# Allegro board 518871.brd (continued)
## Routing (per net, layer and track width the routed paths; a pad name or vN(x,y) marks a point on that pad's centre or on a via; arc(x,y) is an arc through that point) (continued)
VOUT3B_D1: length 45.9
  TOP w0.102: U27.E2 56.68,76.87 56.95,77.14 58.09,77.14
  TOP w0.127: v1(79.76,76.03) 68.92,76.03 68.8,75.91 64.43,75.91 63.92,76.42 60.49,76.42 59.76,77.14 58.09,77.14 ; SW1.11 v1(79.76,78.74)
  LY3 w0.133: v1(79.76,78.74) 80.24,79.22 81.31,79.22 83.1,77.43 85.3,77.43 85.72,77.85 89.66,77.85 89.92,77.6 91.31,77.6 92.84,79.12 93.7,79.12 v1(93.82,79.25)
  BOTTOM w0.127: 93.82,80.64 v1(93.82,79.25) ; v1(79.76,76.03) v1(79.76,78.74) R255.1
VOUT3B_D2: length 44.1
  TOP w0.127: SW1.10 v1(78.49,78.74) ; v1(78.49,75.44) 78.27,75.65 63.92,75.65 63.41,76.16 60.24,76.16 59.56,76.84 U27.E1
  LY3 w0.133: v1(78.49,78.74) 79.23,79.48 81.55,79.48 82.55,78.49 85.85,78.49 86.14,78.2 89.82,78.2 90.05,77.97 91.31,77.97 92.82,79.49 v1(92.82,79.9)
  BOTTOM w0.127: v1(78.49,75.44) v1(78.49,78.74) R251.1 ; 92.82,80.64 v1(92.82,79.9)
VOUT3B_D3: length 44.3
  TOP w0.127: v1(77.22,74.93) 76.52,74.23 63.31,74.23 62.86,74.68 59.56,74.68 58.7,75.54 U27.C1 ; SW1.9 v1(77.22,78.74)
  LY3 w0.133: v1(77.22,78.74) 78.22,79.74 81.8,79.74 82.68,78.87 86.11,78.87 86.52,78.46 90.07,78.46 90.3,78.23 90.93,78.23 v1(91.82,79.12)
  BOTTOM w0.127: v1(91.82,79.12) 92.32,79.62 92.32,80.64 ; v1(77.22,74.93) v1(77.22,78.74) R247.1
VOUT3B_D4: length 43.6
  TOP w0.127: U27.D1 59.19,76.19 59.94,75.44 63.12,75.44 63.63,74.93 72.26,74.93 72.47,75.14 75.74,75.14 v1(75.95,74.93) ; SW1.8 v1(75.95,78.74)
  LY3 w0.133: v1(75.95,78.74) 77.21,80 82.05,80 82.8,79.25 86.36,79.25 86.87,78.74 90.3,78.74 90.42,78.61 90.93,78.61 91.31,78.99 91.31,79.38 v1(91.83,79.89)
  BOTTOM w0.127: R243.1 v1(75.95,78.74) v1(75.95,74.93) ; 91.83,80.64 v1(91.83,79.89)
VOUT3B_D5: length 43.7
  TOP w0.102: 58.09,75.86 57.01,75.86 U27.D2
  TOP w0.127: 58.09,75.86 58.88,75.86 59.69,75.06 62.99,75.06 63.37,74.68 74.63,74.68 v1(74.68,74.72) ; SW1.7 v1(74.68,78.74)
  LY3 w0.133: v1(74.68,78.74) 76.2,80.26 82.3,80.26 82.93,79.63 86.61,79.63 87.12,79.12 v1(90.81,79.12)
  BOTTOM w0.127: v1(74.68,74.72) v1(74.68,78.74) R241.1 ; v1(90.81,79.12) 91.33,79.64 91.33,80.64
VOUT3B_D6: length 43.9
  TOP w0.127: U27.B1 58.33,74.89 59.31,73.91 62.61,73.91 63.12,73.41 77.6,73.41 78.11,73.91 81.41,73.91 81.79,73.53 v1(81.79,73.49)
  LY4 w0.133: v1(81.79,73.49) 81.79,73.91 81.63,74.06 81.18,74.06 81.03,74.22 81.03,74.44 81.18,74.6 81.63,74.6 81.79,74.75 81.79,74.97 81.45,75.31 81.45,76.67 81.18,76.93 81.18,78.13 81.53,78.49 81.53,78.99 81.18,79.35 81.18,80.67 81.53,81.03 81.53,82.3 82.42,83.19 v1(83.44,83.19)
  BOTTOM w0.127: U77.23 86.5,84.34 85.34,83.19 v1(83.44,83.19) 83.44,83.44 RJ25.2
VOUT3B_D7: length 43.5
  TOP w0.127: v1(81.03,73.41) 80.64,73.03 63.08,73.03 62.57,73.53 59.18,73.53 58.16,74.56 57.27,74.56 57.25,74.58 57.2,74.58 56.88,74.89 U27.B2
  LY4 w0.133: v1(83.44,84.45) 82.55,84.45 80.39,82.3 80.39,74.04 v1(81.03,73.41)
  BOTTOM w0.127: U77.24 86.11,84.84 85.72,84.45 v1(83.44,84.45) 83.44,84.71 RJ24.2
VOUT3B_D8: length 56.6
  TOP w0.102: 58.09,75.21 57.01,75.21 U27.C2
  TOP w0.127: 58.09,75.21 58.52,75.21 59.44,74.3 62.74,74.3 63.12,73.91 77.34,73.91 77.98,74.55 91.06,74.55 93.34,76.83 99.19,76.83 v1(100.08,77.72)
  BOTTOM w0.127: U77.60 98.4,83.34 98.83,82.91 99.92,82.91 100.46,83.44 101.35,82.55 101.35,81.03 100.08,79.76 v1(100.08,77.72)
VOUT3B_D9: length 53.2
  TOP w0.102: 58.09,76.49 56.34,76.49 U27.D3
  TOP w0.127: v1(99.06,77.6) 98.55,77.09 91.57,77.09 89.41,74.93 78.11,74.93 77.64,75.4 72.37,75.4 72.28,75.31 63.75,75.31 63.25,75.82 60.07,75.82 59.4,76.49 58.09,76.49
  BOTTOM w0.127: v1(99.06,77.6) 99.31,77.85 99.31,81.66 RJ16.2 99.16,82.58 98.4,82.58 98.13,82.84 U77.61
VOUT3B_D10: length 53
  TOP w0.127: U27.A2 56.68,73.45 57.86,72.27 58.22,72.27 58.34,72.39 v1(63.12,72.39)
  LY3 w0.133: v1(63.12,72.39) 64.26,73.53 79.88,73.53 80.52,74.17 93.98,74.17 94.61,74.8 94.61,75.31 95.5,76.2 v1(98.3,76.2)
  BOTTOM w0.127: v1(98.3,76.2) 98.3,76.45 RJ20.2 98.68,77.34 97.58,78.44 97.58,80.82 97.92,81.15 97.92,82.17 97.75,82.33 96.53,82.33 U77.62
VOUT3B_D11: length 49.9
  TOP w0.102: 56.35,73.51 56.35,74.38 56.03,74.7 U27.B3
  TOP w0.127: v1(62.48,71.97) 62.45,72.01 57.76,72.01 56.35,73.41 56.35,73.51
  LY3 w0.133: v1(62.48,71.97) 62.52,71.97 62.57,71.92 63.8,71.92 65.14,73.27 80.13,73.27 80.77,73.91 83.95,73.91 84.33,73.53 94.74,73.53 v1(96.14,74.93)
  BOTTOM w0.127: v1(96.14,74.93) 96.14,75.18 RJ21.2 96.77,75.82 96.77,77.72 95.82,78.67 95.82,80.64
VOUT3B_D12: length 46.3
  TOP w0.102: U27.C3 56.36,75.21 56.36,74.74 56.53,74.57 56.81,74.57 57.01,74.38 57.01,73.88 57.38,73.51
  TOP w0.127: 57.38,73.51 57.63,73.25 58.09,73.25 58.45,72.9 v1(62.61,72.9)
  LY3 w0.133: v1(62.61,72.9) 63.63,73.91 79.76,73.91 80.35,74.51 92.8,74.51 v1(94.55,76.26)
  BOTTOM w0.127: 95.32,80.64 95.32,78.81 95.12,78.61 RJ19.2 v1(94.55,76.26)
VOUT3B_D13: length 44.5
  TOP w0.127: U27.C4 v3(55.7,75.22)
  LY3 w0.133: v1(92.33,74.93) 80.26,74.93 79.63,74.3 56.63,74.3 v3(55.7,75.22)
  BOTTOM w0.127: v1(92.33,74.93) RJ22.2 92.96,77.22 94.87,79.12 94.87,80.14 94.82,80.18 94.82,80.64
VOUT3B_D14: length 43.9
  TOP w0.127: v1(61.98,71.12) 60.33,71.12 59.69,71.75 57.65,71.75 56.03,73.38 U27.A3
  LY3 w0.133: v1(83.44,73.41) 82.55,73.41 82.04,72.9 65.66,72.9 64.3,71.54 62.4,71.54 v1(61.98,71.12)
  LY4 w0.133: v1(83.44,73.41) v1(83.44,80.64)
  BOTTOM w0.127: U77.21 86.9,83.34 85.85,82.3 85.85,81.53 84.96,80.64 v1(83.44,80.64) 83.44,80.9 RJ18.2
VOUT3B_D15: length 46.5
  TOP w0.102: 56.17,72.87 55.68,73.37 55.68,74.59 U27.B4
  TOP w0.127: v1(61.72,70.23) 59.94,70.23 58.67,71.5 57.55,71.5 56.17,72.87
  LY3 w0.133: v1(61.72,70.23) 63.75,70.23 66.04,72.52 82.42,72.52 v1(82.8,72.9)
  LY4 w0.133: v1(82.8,72.9) 82.8,81.28 v1(83.44,81.92)
  BOTTOM w0.127: U77.22 86.51,83.84 85.47,82.8 85.47,82.3 85.09,81.92 v1(83.44,81.92) 83.44,82.17 RJ23.2
VOUT3B_D16: length 50.9
  TOP w0.102: U27.M1 58.94,81.39 59.18,81.15 59.36,81.15
  TOP w0.127: v1(98.55,87.38) 98.55,85.98 98.15,85.57 96.88,85.57 95.12,83.82 95.12,82.8 93.47,81.15 90.17,81.15 88.77,79.76 83.57,79.76 83.02,80.3 83.02,81.19 81.66,82.55 72.77,82.55 71.25,81.03 68.92,81.03 68.63,80.73 65.9,80.73 65.87,80.7 65.52,80.7 65.5,80.73 62.4,80.73 62.28,80.61 61.93,80.61 61.38,81.15 59.36,81.15
  BOTTOM w0.127: U77.53 97.4,86.84 97.43,86.87 98.04,86.87 v1(98.55,87.38)
VOUT3B_D17: length 47.6
  TOP w0.102: 59.44,81.41 59.15,81.69 56.98,81.69 U27.M2
  TOP w0.127: v1(97.79,86.11) 97.51,85.83 96.64,85.83 94.87,84.05 94.87,83.06 93.35,81.53 90.04,81.53 88.65,80.14 84.84,80.14 83.69,81.28 83.31,81.28 81.66,82.93 72.64,82.93 71.29,81.57 61.76,81.57 61.59,81.41 59.44,81.41
  BOTTOM w0.127: v1(97.79,86.11) 97.52,85.84 U77.55
VOUT3B_D18: length 49.6
  TOP w0.102: U27.L2 56.98,81.04 58.66,81.04 58.8,80.9
  TOP w0.127: 58.8,80.9 58.89,80.81 61.18,80.81 61.63,80.35 62.57,80.35 62.67,80.45 65.98,80.45 66.01,80.48 71.21,80.48 72.9,82.17 81.66,82.17 82.68,81.15 82.68,80.01 83.31,79.38 88.9,79.38 90.3,80.77 93.73,80.77 95.38,82.42 95.38,83.57 97.07,85.26 97.75,85.26 v1(98.17,84.84)
  BOTTOM w0.127: v1(98.17,84.84) 97.67,85.34 U77.56
VOUT3B_D19: length 47.1
  TOP w0.102: U27.L1 58.45,80.74 58.61,80.58
  TOP w0.127: v1(97.4,84.84) 97.01,84.84 95.63,83.46 95.63,82.17 93.85,80.39 90.55,80.39 89.15,78.99 83.19,78.99 82.17,80.01 82.17,80.73 81.11,81.79 73.02,81.79 71.37,80.14 68.96,80.14 68.36,79.54 62.95,79.54 62.61,79.88 60.83,79.88 60.2,80.52 58.67,80.52 58.61,80.58
  BOTTOM w0.127: U77.57 v1(97.4,84.84)
VOUT3B_D20: length 47.1
  TOP w0.127: U27.K3 v3(56.36,79.77)
  LY3 w0.102: 58.09,79.77 v3(56.36,79.77)
  LY3 w0.133: 58.09,79.77 59.8,79.77 60.96,78.61 73.03,78.61 74.94,80.52 82.54,80.52 82.93,80.14 84.45,80.14 86.11,81.79 96.14,81.79 v1(98.17,83.82)
  BOTTOM w0.127: v1(98.17,83.82) 97.65,84.34 U77.58
VOUT3B_D21: length 46.8
  TOP w0.102: 58.55,80.14 58.29,80.39 56.98,80.39 U27.K2
  TOP w0.127: v1(97.39,83.84) 96.92,83.84 95.89,82.8 95.89,81.79 94.36,80.26 94.09,80.26 92.43,78.61 81.66,78.61 81.28,78.23 74.42,78.23 74.04,78.61 74.04,79.25 73.53,79.76 69.09,79.76 68.45,79.12 66.23,79.12 65.82,78.71 63.02,78.71 62.1,79.63 60.58,79.63 60.07,80.14 58.55,80.14
  BOTTOM w0.127: U77.59 v1(97.39,83.84)
VOUT3B_D22: length 45.3
  TOP w0.127: U27.J1 57.72,79.44 58.17,78.99 59.69,78.99 60.07,78.61 61.72,78.61 62.39,77.95 66.12,77.95 66.27,77.8 66.27,77.49 66.42,77.34 66.63,77.34 66.78,77.49 66.78,77.8 66.93,77.95 67.14,77.95 67.29,77.8 67.29,77.49 67.44,77.34 67.65,77.34 67.8,77.49 67.8,77.8 67.95,77.95 69.58,77.95 69.73,77.8 69.73,77.36 69.88,77.22 70.09,77.22 70.24,77.36 70.24,77.8 70.39,77.95 70.6,77.95 70.75,77.8 70.75,77.36 70.89,77.22 71.1,77.22 71.25,77.36 71.25,77.8 71.4,77.95 71.61,77.95 71.76,77.8 71.76,77.36 71.91,77.22 72.12,77.22 72.27,77.36 72.27,77.8 72.42,77.95 72.67,77.95 73.41,77.22 v1(86.11,77.22)
  BOTTOM w0.127: v1(86.11,77.22) 86.61,77.72 86.61,77.98 86.47,78.13 85.49,78.13 85.34,78.28 85.34,78.49 85.49,78.63 86.47,78.63 86.61,78.78 86.61,78.99 86.47,79.14 85.49,79.14 85.34,79.29 85.34,79.5 85.49,79.65 86.47,79.65 86.61,79.8 86.61,81.92 87.04,82.34 U77.19
VOUT3B_D23: length 44.9
  TOP w0.102: 58.42,79.76 58.08,80.09 U27.K1
  TOP w0.127: 58.42,79.76 59.94,79.76 60.45,79.25 61.98,79.25 62.77,78.46 65.93,78.46 66.08,78.61 69.43,78.61 69.57,78.76 69.57,79.23 69.72,79.38 69.93,79.38 70.08,79.23 70.08,78.76 70.23,78.61 70.44,78.61 70.59,78.76 70.59,79.23 70.74,79.38 70.95,79.38 71.1,79.23 71.1,78.76 71.25,78.61 71.46,78.61 71.61,78.76 71.61,79.23 71.75,79.38 71.97,79.38 72.11,79.23 72.11,78.76 72.26,78.61 72.47,78.61 72.62,78.76 72.62,79.23 72.77,79.38 72.98,79.38 73.13,79.23 73.13,78.76 73.91,77.98 v1(83.95,77.98)
  BOTTOM w0.127: v1(83.95,77.98) 84.71,77.98 84.84,78.11 84.84,78.4 84.69,78.55 82.06,78.55 81.92,78.69 81.92,78.91 82.06,79.05 84.69,79.05 84.84,79.2 84.84,80.01 86.23,81.41 86.23,81.92 87.16,82.84 U77.20
VOUT3B_DE: length 44.4
  TOP w0.102: 58.17,79.5 57.91,79.76 56.99,79.76 U27.J2
  TOP w0.127: 58.17,79.5 58.29,79.38 59.82,79.38 60.32,78.87 61.85,78.87 62.51,78.2 73.05,78.2 73.7,77.56 85.56,77.56 85.72,77.72 86.61,77.72 v1(87.12,77.22)
  BOTTOM w0.127: U77.18 87.17,81.84 87,81.66 87,80.14 87.12,80.01 87.12,79.62 87.27,79.47 89.01,79.47 89.15,79.32 89.15,79.11 89.01,78.96 87.27,78.96 87.12,78.82 87.12,78.61 87.27,78.46 89.01,78.46 89.15,78.31 89.15,78.1 89.01,77.95 87.27,77.95 87.12,77.8 v1(87.12,77.22)
VOUT3B_HSYNC: length 40.7
  TOP w0.127: U27.K4 v3(55.71,79.77)
  LY3 w0.102: v3(55.71,79.77) 56.1,79.38 58.09,79.38
  LY3 w0.133: 58.09,79.38 59.56,79.38 60.71,78.23 62.74,78.23 63.25,77.72 65.35,77.72 65.49,77.87 81.26,77.87 83.06,76.07 89.28,76.07 v1(89.98,76.77)
  BOTTOM w0.127: v1(89.98,76.77) 90.33,77.12 90.33,80.64
VOUT3B_VSYNC: length 44.5
  TOP w0.127: v1(89.03,77.22) 88.61,76.8 88.22,76.8 88.07,76.65 88.07,75.97 87.92,75.82 87.71,75.82 87.56,75.97 87.56,76.65 87.41,76.8 87.2,76.8 87.05,76.65 87.05,75.97 86.9,75.82 86.69,75.82 86.55,75.97 86.55,76.65 86.4,76.8 86.19,76.8 86.04,76.65 86.04,75.97 85.89,75.82 85.68,75.82 85.53,75.97 85.53,76.65 85.38,76.8 85.17,76.8 85.02,76.65 85.02,75.97 84.87,75.82 84.66,75.82 84.51,75.97 84.51,76.65 84.36,76.8 84.15,76.8 84.01,76.65 84.01,75.97 83.86,75.82 83.65,75.82 83.5,75.97 83.5,76.65 83.35,76.8 68.75,76.8 68.47,77.08 65.29,77.08 64.77,77.6 62.36,77.6 61.59,78.36 59.82,78.36 59.56,78.61 57.91,78.61 57.73,78.79 U27.H1
  BOTTOM w0.127: v1(89.03,77.22) 89.83,78.01 89.83,80.64
VREF_DBG: length 21.4
  TOP w0.203: 83.57,51.44 83.57,49.02 83.19,48.64 83.19,46.61 82.72,46.14 82.72,45.09 80.56,42.93 78.49,42.93 77.98,43.43 76.76,43.43 76.25,43.94 J14.12
  TOP w0.305: J14.1 79.32,51.51 79.63,51.82 81.28,51.82 81.66,51.44 83.57,51.44
VSYS_3V3: length 6.2
  TOP w0.305: U600.4 v1(64.77,97.03) ; U42.4 v1(73.1,25.32) ; 40.51,17.91 v1(40.51,17.08) ; R22.2 v1(34.04,17.21) ; C554.2 v1(36.32,29.59) ; U603.3 v1(63.83,103.94)
  BOTTOM w0.305: v1(36.32,29.59) 36.34,29.61 U76.4 ; R217.2 37.21,20.07 36.96,19.81 36.96,19.8 v1(36.95,19.79)
  vias: v1(13.46,45.47) v1(13.59,44.58) v1(13.72,27.05) v1(14.73,33.66) v1(14.99,44.2) v1(15.24,27.05) v1(15.75,33.66) v1(15.88,44.2) v1(16.76,33.66) v1(17.78,33.66) v1(18.8,33.66) v1(35.18,57.66) v1(35.18,47.12) v1(35.94,57.66) v1(36.2,56.9) v1(36.2,55.75) v1(36.2,49.02) v1(36.21,48.01) v1(36.2,47.12) v1(36.83,57.66) v1(36.96,56.39) v1(36.96,48.39) v1(36.96,47.37) v1(38.35,58.55) v1(39.12,58.55) v1(42.42,56.39) v1(42.42,48.39) v1(42.42,47.12) v1(42.49,57.53) v1(42.93,49.02) v1(42.93,47.75) v1(43.05,56.9) v1(43.05,55.88) v1(63.75,92.96) v1(64.26,94.49) v1(64.26,93.6) v1(67.56,104.01) v1(68.58,35.94) v1(68.71,28.32) v1(69.47,35.94) v1(69.6,28.32) v1(70.1,34.42) v1(70.61,35.94) v1(74.3,104.01)
VSYS_5V0: length 21.8
  TOP w0.203: v1(46.1,111.12) 46.41,111.43 U17.10
  TOP w0.305: C617.2 v1(72.26,92.96) U604.2 ; 73.1,20.95 TP51.1 ; TP51.1 74.47,20.95 ; TP51.1 73.79,20.27 ; TP51.1 73.79,21.64 ; U18.16 33.65,18.93 v1(34.04,18.54) ; R31.1 R30.2 ; R30.2 R28.2 ; R30.2 v1(42.55,112.14) ; U601.4 v1(70.79,32.64) ; U70.4 v1(110.57,85.9) ; R143.2 v1(74.3,30.73) ; U79.3 v1(102.87,59.56)
  LY3 w0.635: TP51.1 73.79,21.64 ; TP51.1 74.47,20.95 ; TP51.1 73.1,20.95 ; TP51.1 73.79,20.27
  BOTTOM w0.203: v1(46.1,111.12) C269.1
  BOTTOM w0.305: v1(74.17,93.73) 74.17,94.11 R606.2 ; v1(46.1,111.12) 45.59,111.12 45.21,110.74 43.94,110.74 v1(42.55,112.14) ; C514.1 v1(102.87,59.56)
  vias: v1(72.9,23.5) v1(72.9,22.73) v1(72.9,21.46) v1(72.9,20.45) v1(75.06,21.46)
VTT_DDR:
  vias: v1(5.08,67.31) v1(7.24,67.31) v1(10.03,67.31) v1(10.67,56.26) v1(10.67,55.24) v1(10.67,54.1) v1(10.67,53.09) v1(10.67,51.94) v1(10.67,50.93) v1(11.68,49.78) v1(12.7,67.31) v1(15.37,67.31) v1(18.16,67.18) v1(19.68,67.18) v1(20.83,67.18)
N16778201: length 18.6
  TOP w0.127: v1(125.81,88.19) 125.35,88.65 115.06,88.65 v1(114.43,89.28)
  BOTTOM w0.127: P10.9 v1(125.81,88.19) ; v1(114.43,89.28) 111.89,89.28 111.37,88.77 U69.5 109.1,88.77 R411.2
N16778260: length 2
  TOP w0.127: 118.24,87.38 118.24,87.97 v1(118.4,88.14)
  BOTTOM w0.127: P10.10 118.36,88.1 v1(118.4,88.14)
N16778400: length 2
  TOP w0.254: C543.1 v1(113.65,88.77)
  BOTTOM w0.254: v1(113.65,88.77) 113.64,88.77 U69.1
N16778910: length 1.9
  TOP w0.254: U70.6 108.35,84.83 108.22,84.96 C547.1
N22073312: length 1.6
  TOP w0.127: U31.P6 v1(81.77,57.74)
  BOTTOM w0.127: R299.2 81.79,57.73 v1(81.77,57.74)
N22234321: length 14.2
  TOP w0.127: U27.G21 v3(44.65,77.82)
  LY4 w0.133: v3(44.65,77.82) 42.42,75.58 42.42,73.66 41.47,72.71 38.28,72.71 36.78,71.22 v1(35.43,71.22)
  BOTTOM w0.127: R266.2 35.4,71.25 v1(35.43,71.22)
N22234323: length 11.4
  TOP w0.102: U27.F23 42.68,77.14 42.25,77.14 42.08,76.97 42.08,76.75 41.87,76.54 40.97,76.54
  TOP w0.127: v1(35.69,72.14) 36.32,72.77 38.48,72.77 38.99,73.28 38.99,74.56 40.97,76.54
  BOTTOM w0.127: R265.2 v1(35.69,72.14)
N26762656: length 2.2
  TOP w0.127: v1(45.34,114.43) 45.63,114.14 U17.4
  BOTTOM w0.127: R216.2 45.59,114.17 v1(45.34,114.43)
N26762977: length 2
  TOP w0.127: R33.2 47.12,110.24 47.17,110.29 U17.11
N27139839: length 20.4
  TOP w0.102: U27.J20 44.39,79.44 43.98,79.03 43.98,77.76 42.71,76.49 42.25,76.49 42.03,76.27 42.03,76.07 41.81,75.84 40.97,75.84
  TOP w0.127: 40.97,75.84 40.79,75.84 39.5,74.55 39.5,72.77 36.96,70.23 33.53,70.23 v1(31.76,68.47)
  BOTTOM w0.127: R264.1 31.75,68.45 v1(31.76,68.47)
N27139840: length 12.7
  TOP w0.127: U27.K25 39.45,80.09 38.1,78.74 35.7,78.74 31.77,74.8 R70.1
N27143878: length 4.9
  TOP w0.127: U27.H25 39.3,78.79 37.85,77.34 R75.1
N27144522: length 8
  TOP w0.102: 58.09,84.97 56.35,84.97 U27.U3
  TOP w0.127: 58.09,84.97 59.99,84.97 60.02,85 62.01,85 62.35,85.34 63,85.34 63.25,85.09 R66.2
N27225962: length 15.9
  TOP w0.127: U27.E14 48.88,76.84 v3(48.55,76.52)
  LY3 w0.133: v1(54.61,66.55) 51.05,66.55 50.2,67.41 50.2,73.25 49.02,74.43 49.02,76.05 v3(48.55,76.52)
  BOTTOM w0.127: 54.61,65.66 v1(54.61,66.55)
N27380264: length 4.4
  TOP w0.127: v1(75.69,53.85) 75.25,53.4 75.25,51.51 J14.15
  BOTTOM w0.127: R309.2 75.96,52.32 76.2,52.56 76.2,53.34 v1(75.69,53.85)
N27473363: length 2.5
  TOP w0.127: U17.3 45.86,114.54 45.55,114.85 44.11,114.85 R25.2
N29751222: length 1.7
  TOP w0.254: v2(16.38,120.27) 16.51,120.14 C81.1
  BOTTOM w0.254: v2(16.38,120.27) 17.27,120.27 U52.16
N29751238: length 1
  BOTTOM w0.254: U52.19 v1(19.06,122.05)
N29751250: length 3.7
  TOP w0.305: R51.2 v2(12.95,124.21)
  BOTTOM w0.305: v2(10.79,122.3) 11.05,122.3 v2(12.95,124.21)
N29751338: length 7.9
  TOP w0.14: v1(15.24,121.67) R52.1 C72.1 R51.1
  BOTTOM w0.127: U52.18 18.56,122.03 18.16,122.43 16,122.43 v1(15.24,121.67)
N29751389: length 1.7
  TOP w0.14: R55.2 17.13,117.74 v2(16.39,117.74)
  BOTTOM w0.14: U52.11 v2(16.39,117.74)
N29751493: length 1.9
  BOTTOM w0.14: U52.30 23.73,117.74 23.74,117.73 R232.2
N30095792: length 2.8
  TOP w0.127: v1(92.46,48.26) 93.37,49.17 U40.2
  BOTTOM w0.127: R346.2 v1(92.46,48.26)
N30095794: length 2.8
  TOP w0.127: TP49.1 98.92,53.7 U40.16
N30127037: length 9.2
  TOP w0.102: 42.68,73.51 42.68,75.19 U27.C23
  TOP w0.127: 42.68,73.51 42.68,71.64 42.67,71.63 42.67,67.56 43.05,67.18 R97.2
N30256264: length 3.7
  TOP w0.102: 12.71,89.53 U23.L8
  TOP w0.127: 12.71,89.53 12.71,86.37 R64.1
N30256273: length 3.7
  TOP w0.102: 12.71,75.31 U29.L8
  TOP w0.127: R76.1 12.71,72.15 12.71,75.31
N30257754: length 4.7
  TOP w0.305: U35.1 13.28,48.46 14.1,49.28 14.1,50.16 R118.2 C160.2
N30258027: length 1.9
  TOP w0.14: R128.1 11.18,44.83 11.31,44.97 U35.7
N30258029: length 1.9
  TOP w0.254: U35.9 12.31,44.83
  TOP w0.305: 12.31,44.83 12.45,44.7 R129.1
N30258277: length 2.9
  TOP w0.305: U35.5 10.21,48.46 10.16,48.51 R120.1 9.02,48.26 8,48.26
N30258482: length 2.8
  TOP w0.508: v1(16.89,67.31) 17.27,67.69 R94.1
  BOTTOM w0.508: C416.1 16.64,67.06 v1(16.89,67.31) 16.64,67.56 R278.1
N30411655: length 3.8
  TOP w0.127: U22.7 v1(11.56,110.24)
  BOTTOM w0.127: TP18.1 v1(11.56,110.24) R235.1
N30491879: length 11.5
  TOP w0.127: v3(49.85,87.57) U27.AA12
  BOTTOM w0.127: v3(49.85,87.57) 49.85,88.21 50.55,88.9 50.55,89.41 51.18,90.04 51.18,94.74 Y3.2 51.23,95.1 50.83,95.5 50.71,95.5 50.11,96.1 Y3.4 50.16,96.27 C276.2
N30491883: length 9.8
  TOP w0.102: U27.Y12 49.85,86.92 49.33,86.92 49.19,86.92 48.74,87.37 48.74,87.72 49.02,88.01 49.02,89.41 49.28,89.66
  TOP w0.127: 49.28,89.66 49.28,92.46 v1(49.53,92.71)
  BOTTOM w0.127: Y3.3 50.16,94.74 C292.1 50.16,93.34 v1(49.53,92.71)
N30491911: length 11.2
  TOP w0.127: U27.AB12 50.04,88.04 50.04,88.39 51.31,89.66 51.31,90.55 51.94,91.19 v1(51.94,93.73)
  BOTTOM w0.127: 51.18,97.54 51.23,97.49 Y3.1 51.74,96.22 52.07,95.89 52.07,93.85 v1(51.94,93.73)
N30492439: length 6.1
  TOP w0.127: U40.5 94.87,49.15 96.01,48.01 v1(96.01,45.97) 95.94,45.9 Y2.3
  BOTTOM w0.127: C506.1 v1(96.01,45.97)
N30492465: length 3.6
  TOP w0.127: Y2.1 94.06,48.18 94.02,48.22 v1(94.02,48.26) 94.37,48.61 U40.4
  BOTTOM w0.127: C503.1 93.98,48.22 v1(94.02,48.26)
N30512853: length 2.5
  TOP w0.112: L44.1 109.26,50.23 109.75,50.72 110.31,50.72 C232.2
N30512862: length 2.4
  TOP w0.112: C233.2 110.39,51.08 109.83,51.08 109.28,51.63 L44.2
N31206842: length 11.8
  TOP w0.305: Q3.4 119.25,18.92 ; 119.25,18.92 119.76,18.41 121.16,18.41 121.47,18.72 U16.2 ; 119.25,18.92 119.25,20.7 121.16,22.61 121.65,22.61 122.12,23.08 U16.6
N31206856: length 5.5
  TOP w0.305: C30.1 121.09,21.34 120.82,21.07 U16.1
N31206860: length 6
  TOP w0.305: U16.7 121.47,25.57 121.94,26.04 123.95,26.04 124.97,25.02 C30.2
N31206880: length 18.1
  LY4 w0.133: v1(117.35,41.4) 120.02,38.73 v1(120.02,25.4)
  BOTTOM w0.305: R202.2 v1(117.35,41.4)
N31207095: length 2.1
  TOP w0.127: DS1.2 118.52,43.03 v1(118.36,43.18)
  BOTTOM w0.127: v1(118.36,43.18) R202.1
N31208453: length 2.7
  TOP w0.203: U18.13 v1(31.5,19.68)
  BOTTOM w0.203: R213.2 31.5,18.54 v1(31.5,19.68)
N31208462: length 2
  TOP w0.203: U18.14 32.65,19.19 v1(32.26,18.8)
  BOTTOM w0.203: R214.1 32,18.54 v1(32.26,18.8)
N31208471: length 2.9
  TOP w0.203: v1(30.35,22.99) 31,22.34 U18.8
  BOTTOM w0.203: R219.2 29.84,23.5 v1(30.35,22.99)
N31208480: length 1.8
  TOP w0.203: v1(30.99,23.5) 30.99,23.04 31.19,22.83 U18.7
  BOTTOM w0.203: R220.1 v1(30.99,23.5)
N31208503: length 13.8
  LY3 w0.305: v1(18.96,24.09) 20.14,25.27 v1(29.08,25.27)
  BOTTOM w0.305: R220.2 R219.1 v1(29.08,25.27) ; Q10.4 v1(18.96,24.09)
N31208524: length 7.6
  BOTTOM w0.305: Q9.4 27.6,20.41 29.97,18.03 29.97,17.2 30.28,16.89 R213.1 R214.2
N31208551: length 19.3
  TOP w0.203: C39.1 29.97,18.92 v1(30.61,19.56) 30.61,20.07 30.89,20.35 U18.12 ; R18.1 v1(38.23,16.13)
  LY4 w0.203: v1(38.23,16.13) 37.59,15.49 32.84,15.49 32,16.33 32,18.16 v1(30.61,19.56)
  BOTTOM w0.203: v1(30.61,19.56) 27.05,23.11
  vias: v1(19.3,23.24) v1(19.3,22.48) v1(21.59,23.88) v1(21.59,23.11) v1(21.59,22.35) v1(22.48,23.88) v1(22.48,23.11) v1(22.48,22.35) v1(24.13,23.24) v1(24.13,22.35) v1(24.89,23.24) v1(24.89,22.35) v1(25.65,23.24) v1(25.65,22.35)
N31208672: length 3.8
  TOP w0.203: U18.11 29.99,20.84 C39.2 D5.1
N31208960: length 1.4
  BOTTOM w0.508: C270.1 R225.1
N31209649: length 6.2
  TOP w0.203: U18.18 34.65,19.46 36.07,18.03 C36.2 R428.1 R18.2
N31209654: length 4.8
  TOP w0.203: U18.17 34.15,19.19 35.05,18.29 C36.1 R22.1 R428.2
N31222024: length 3.3
  TOP w0.305: R39.2 35.56,24.89 v1(35.18,24.51) 34.65,23.98 U18.1
  BOTTOM w0.305: R221.1 35.43,24.26 v1(35.18,24.51)
N31222132: length 1.4
  TOP w0.203: C41.2 37.34,21.59 37.21,21.46
N31222198: length 3.5
  TOP w0.203: U18.20 35.93,20.84 36.32,20.45 R29.2 38.48,20.45 C40.1
N31222241: length 3.5
  TOP w0.203: U18.24 35.31,23.62 36.83,25.15 C51.2
N31222246: length 2.5
  TOP w0.203: U18.22 35.81,21.84 36.83,22.86 C43.2
N31222265: length 3.6
  TOP w0.203: R36.2 R35.1 31.31,25.08 31.31,24.7 32.16,23.85 U18.6
N31222285: length 3.4
  TOP w0.203: U18.5 32.65,23.99 32.31,24.33 32.31,24.94 C54.2 R34.1
N31222303: length 2.1
  TOP w0.203: U18.4 33.15,24.38 v1(33.02,24.51)
  BOTTOM w0.203: R222.2 v1(33.02,24.51)
N31222717: length 1.1
  TOP w0.203: R24.2 R23.1
N31975868: length 16.2
  TOP w0.127: TP32.1 44.7,64.26 44.7,66.9 44.04,67.56 44.04,68.86 43.43,69.47 43.43,71.5 44.65,72.72 44.65,77.17 U27.F20
N32593135: length 6
  TOP w0.102: 55.06,73.51 55.06,74.56 U27.B5
  TOP w0.127: 55.06,73.51 55.06,73.27 57.46,70.87 57.78,70.87 R99.2
N32595277: length 15.8
  TOP w0.102: 40.97,79.76 42.05,79.76 42.06,79.77 U27.K24
  TOP w0.127: 40.97,79.76 39.51,79.76 38.1,78.36 36.11,78.36 33.44,75.69 v1(33.4,75.69)
  BOTTOM w0.127: v1(33.4,75.69) C375.2 R263.1 29.59,74.55
N33095449: length 3.9
  BOTTOM w0.127: U76.3 37.24,32.36 R433.1 38.48,31.11 38.48,30.61 38.7,30.39 Q12.3
N33095497: length 11.3
  BOTTOM w0.127: R431.1 C553.1 R432.1 ; R432.1 35.69,28.96 35.04,29.61 U76.5 33.93,30.38 33.86,30.3 D24.1 ; R432.1 Q12.2
N33095499: length 3.6
  BOTTOM w0.127: R430.1 41.69,32.35 Q12.6 40.4,32.87 40.27,32.99 39.88,32.99 39.75,32.87 Q12.5
N33309281: length 2.4
  TOP w0.127: U79.1 v1(100.33,56.77)
  BOTTOM w0.127: v1(100.33,56.77) R372.2
N33309290: length 4.2
  BOTTOM w0.127: R388.2 R152.1 C525.1
N33309297: length 2.4
  TOP w0.127: U79.4 v1(104.14,56.77)
  BOTTOM w0.127: v1(104.14,56.77) R371.2
N33309347: length 3.4
  TOP w0.127: U79.14 v1(100.33,62.36)
  BOTTOM w0.127: R441.2 R426.2 v1(100.33,62.36)
N33312629: length 2.4
  TOP w0.127: U79.9 v1(106.68,65.15)
  BOTTOM w0.127: v1(106.68,65.15) R435.1
N33314378: length 3.4
  TOP w0.127: U79.7 v1(107.95,59.56)
  BOTTOM w0.127: R436.2 R446.1 v1(107.95,59.56)
N33322259: length 3
  TOP w0.127: U79.6 v1(106.68,59.56)
  BOTTOM w0.127: R438.2 v1(106.68,59.56) R440.2
N33322262: length 3.4
  TOP w0.127: U79.8 v1(107.95,62.36)
  BOTTOM w0.127: v1(107.95,62.36) R439.2 R382.2
N33325781: length 5.2
  BOTTOM w0.127: RJ28.2 83.82,87 84.96,87 85.6,86.36 86.74,86.36 86.76,86.34 U77.27
N33325790: length 4.9
  BOTTOM w0.127: U77.26 86.75,85.84 86.74,85.85 86.49,85.85 86.36,85.72 83.69,85.72 RJ30.2
N33325799: length 4.7
  BOTTOM w0.127: 100.46,86.36 99.82,85.72 99.19,85.72 98.3,86.61 97.54,86.61 97.26,86.34 U77.54
N33329532: length 7.1
  BOTTOM w0.127: 86.69,96.65 86.69,92.65 TP67.1
N33330487: length 4.9
  TOP w0.102: 58.09,77.84 56.33,77.84 U27.G3
  TOP w0.127: R445.2 60.33,77.6 60.08,77.84 58.09,77.84
N33333072: length 3.1
  TOP w0.127: U26.7 v1(48.65,121.93) 49.14,121.43 U26.8
  BOTTOM w0.127: v1(48.65,121.93) 48.9,122.17 R249.2
N33357651: length 6.2
  TOP w0.102: 53.24,90.58 53.21,90.55 53.21,89.66 52.12,88.57 51.51,88.57 U27.AC10
  TOP w0.127: R447.1 54.61,91.95 53.24,90.58
N33390062: length 9.9
  TOP w0.508: R450.2 v1(114.05,48.26) 113.79,48.01 C569.2 R448.2 ; 114.05,52.7 v1(114.05,53.47)
  BOTTOM w0.508: v1(114.05,53.47) v1(114.05,48.26)
N33412406: length 2
  TOP w0.132: U602.3 38.87,48.4 38.86,48.39 R600.1
N33413294: length 1.6
  TOP w0.254: 74.3,33.91 73.83,33.91 73.7,33.79 U601.6
N33413462: length 1.4
  TOP w0.132: Q600.3 75.15,95.59 v2(75.06,95.5)
  BOTTOM w0.132: v2(75.06,95.5) 75.44,95.89 R605.1
N33413491: length 3.5
  TOP w0.127: Q600.6 76.98,93.11 76.83,92.96 76.45,92.96 76.33,93.09 Q600.5 v1(76.33,94.49)
  BOTTOM w0.127: R606.1 v1(76.33,94.49)
N33414592: length 2.8
  TOP w0.203: R143.1 73.53,28.19 72.9,28.19 72.5,27.8 U42.5
N33414630: length 5
  TOP w0.203: U42.3 72,24.97 72.21,24.77 R141.2 R140.1 C220.2
N33426865: length 22.7
  TOP w0.127: SW2.3 v1(25.53,38.35)
  LY4 w0.133: v1(36.07,23.5) 36.07,25.4 34.54,26.92 34.54,28.19 30.99,31.75 30.99,34.67 27.3,38.35 v1(25.53,38.35)
  BOTTOM w0.254: R218.1 v1(36.07,23.5)
N33434554: length 2.9
  TOP w0.127: U78.4 20.06,51.44 19.94,51.56 19.94,51.82 20.06,51.94 U78.3
N33509800: length 2.2
  TOP w0.305: U606.30 v1(112.47,108.91)
  BOTTOM w0.305: R620.2 111.83,108.91 v1(112.47,108.91)
N33509804: length 7.1
  TOP w0.305: Q603.4 104.61,109.69 v1(104.52,109.6)
  BOTTOM w0.305: R620.1 105.54,108.58 v1(104.52,109.6)
N33509815: length 1.7
  TOP w0.508: 114.05,104.68 114.93,105.56 U606.1
N33509819: length 1.2
  TOP w0.508: U606.2 115.73,104.81
N33509839: length 4.8
  TOP w0.508: U606.28 110.45,110.51 C631.2 R621.1
N33509953: length 3.3
  TOP w0.508: U606.31 112.56,108.11 111.43,106.98 C634.2
N33510014:
  vias: v1(113.79,113.79) v1(114.43,115.44)
N33510050:
  vias: v1(116.33,115.44) v1(117.22,115.57)
N33510080: length 2.8
  TOP w0.508: R623.2 120.4,104.27 119.73,104.94 U606.7
N33529839: length 1.5
  TOP w0.508: R624.1 C636.2
N33635218: length 2.3
  BOTTOM w0.127: R627.1 87.89,90.83 88.11,90.83 88.83,90.12 U77.34
N33635221: length 2.1
  BOTTOM w0.127: U77.33 88.33,90.01 87.88,90.45 87.3,90.45 R627.2
N3026308320: length 5.1
  TOP w0.102: 51.15,73.51 51.15,74.57 U27.B11
  TOP w0.127: 51.15,73.51 51.15,71.6 50.8,71.25 50.8,70.57 R101.2

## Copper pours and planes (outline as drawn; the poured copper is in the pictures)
GND on TOP: 65.91,106.55 66.17,106.3 66.17,105.03 66.04,104.9 66.04,100.08 66.17,99.95 66.17,98.93 65.91,98.68 65.28,98.68 65.02,98.93 65.02,99.95 65.28,100.2 65.28,104.9 65.02,105.16 65.02,106.3 65.28,106.55
GND on TOP: 0.64,10.79 0.64,127 132.72,127 132.72,10.79 ; 12 cut-outs
GND on TOP: 70.74,20.45 70.74,24.51 71.12,24.89 71.12,25.91 73.15,25.91 73.66,25.4 74.04,25.4 74.42,25.78 74.42,26.92 74.17,27.18 73.28,27.18 72.77,26.67 68.58,26.67 68.2,26.29 68.2,20.95 69.09,20.07 70.36,20.07
GND on TOP: 72.77,106.55 73.03,106.3 73.03,105.03 72.9,104.9 72.9,100.08 73.03,99.95 73.03,98.93 72.77,98.68 72.14,98.68 71.88,98.93 71.88,99.95 72.14,100.2 72.14,104.9 71.88,105.16 71.88,106.3 72.14,106.55
GND on TOP: 100.2,36.32 100.2,29.46 106.81,29.46 106.81,36.32
GND on TOP: 39.75,53.47 39.75,58.04 40.13,58.42 41.4,58.42 41.91,57.91 41.91,56.64 41.4,56.13 40.51,56.13 40.01,55.63 40.01,51.18 39.62,51.18 39.5,51.05 39.5,50.16 39.24,50.16 39.24,53.47
GND on TOP: 30.73,46.74 29.72,47.75 29.72,49.15 29.97,49.4 34.16,49.4 34.16,51.94 33.91,52.2 33.91,52.45 34.16,52.7 34.16,55.24 34.04,55.37 29.97,55.37 29.72,55.63 29.72,57.4 30.35,58.04 34.42,58.04 34.67,57.78 34.67,55.5 34.8,55.37 34.8,52.7 35.05,52.45 35.05,52.2 34.8,51.94 34.8,47.5 34.04,46.74
GND on TOP: 64.9,92.58 64.9,94.11 65.28,94.49 65.28,95.5 64.14,95.5 63.75,95.12 62.23,95.12 61.98,95.38 61.98,96.14 62.23,96.39 63.88,96.39 64.14,96.14 65.28,96.14 65.28,96.77 66.29,96.77 66.29,92.58 66.04,92.33 65.15,92.33
GND on BOTTOM: 29.59,28.45 26.16,28.45 25.65,28.96 25.65,29.97 25.27,30.35 23.11,30.35 22.48,30.99 22.48,31.88 23.75,33.15 28.96,33.15 30.73,31.37 30.73,29.59
GND on BOTTOM: 0.64,10.79 0.64,127 132.72,127 132.72,10.79 ; 2 cut-outs
GND on L2_GND: 132.72,10.79 0.64,10.79 0.64,127 132.72,127
GND on LY3: 45.72,79.38 45.72,78.36 45.85,78.23 47.88,78.23 48.51,78.87 51.69,78.87 52.32,78.23 53.09,78.23 53.21,78.36 53.21,78.49 52.07,79.63 52.07,79.88 52.7,80.52 52.7,81.15 52.45,81.41 51.82,81.41 51.05,80.64 51.05,80.39 50.8,80.14 50.04,80.14 49.53,80.64 47.24,80.64 46.48,79.88 46.48,79.63 46.23,79.38
GND on LY4: 0.64,127 132.72,127 132.72,10.79 0.64,10.79
VBAT on TOP: 117.22,37.47 130.94,37.47 130.94,26.67 130.3,26.04 130.3,24.38 130.94,23.75 130.94,14.73 128.91,12.7 114.05,12.7 112.9,13.84 112.9,19.94 117.47,19.94 117.47,18.03 121.67,18.03 122.56,18.92 122.56,20.45 125.86,20.45 126.24,20.83 126.24,25.27 124.84,26.67 117.22,26.67
VBAT_SYS on TOP: 103.63,12.7 15.24,12.7 15.24,18.41 15.88,19.05 23.5,19.05 24.13,19.68 27.3,19.68 28.57,18.41 28.57,16.51 29.21,15.88 31.11,15.88 31.75,16.51 31.62,16.64 31.62,17.65 33.02,19.05 33.02,20.07 33.4,20.07 33.4,18.54 33.66,18.29 33.66,16.51 40.64,16.51 44.45,20.32 67.31,20.32 68.58,19.05 76.2,19.05 81.92,24.77 94.61,24.77 97.66,27.81 103.5,27.81 105.66,25.65 105.66,14.73
VBAT_SYS on TOP: 97.79,121.03 97.79,116.59 96.65,115.44 96.65,112.14 96.52,112.01 85.98,112.01 83.69,114.3 83.69,119.38 86.49,119.38 88.14,121.03
VBAT_SYS on BOTTOM: 96.39,115.95 97.66,117.22 97.66,120.65 85.6,120.65 85.6,116.71 86.36,115.95
VBAT_SYS on BOTTOM: 27.18,19.68 29.34,17.53 29.34,16.64 29.59,16.38 32.13,16.38 32.51,16.76 32.51,19.18 36.96,19.18 37.85,20.07 37.85,20.95 36.83,21.97 36.83,22.73 37.59,23.5 39.37,23.5 40.39,24.51 40.39,26.8 41.4,27.81 41.4,30.86 41.78,31.24 42.29,31.24 42.67,30.86 42.67,24.38 41.15,22.86 41.15,13.72 40.01,12.57 17.78,12.57 16.13,14.22 16.13,17.65 17.14,18.67 20.19,18.67 21.21,19.68
VBAT_SYS on LY5_PWR: 122.17,38.61 76.07,38.61 76.07,33.66 64.01,33.66 64.01,38.61 40.13,38.61 40.13,16.26 33.78,16.26 29.72,20.32 16,20.32 16,10.79 132.72,10.79 132.72,127 84.96,127 84.84,126.87 84.84,115.82 85.85,114.81 112.39,114.81 117.6,109.6 117.6,103.63 119.95,101.28 119.95,75.88 111.63,67.56 111.63,65.53 109.6,63.5 105.66,63.5 105.16,62.99 105.16,61.21 105.79,60.58 111.38,60.58 114.05,63.25 120.52,63.25 122.17,61.59
VCC_LED_30V on TOP: 98.17,116.71 98.17,119.76 98.55,120.14 112.9,120.14 114.43,121.67 121.54,121.67 121.79,121.41 121.79,118.75 120.52,117.47 113.54,117.47 113.03,116.97 113.03,116.46 112.52,115.95 104.39,115.95 104.01,115.57 104.01,113.67 103.5,113.16 102.74,113.16 102.11,112.52 102.11,109.98 97.54,109.98 97.03,110.49 97.03,115.57
VCC_LED_30V on BOTTOM: 110.49,115.95 111.12,116.59 111.12,120.14 98.04,120.14 98.04,116.84 98.93,115.95
VCC_LED_30V on LY4: 100.08,115.95 99.06,116.97 99.06,123.19 100.71,124.84 128.14,124.84 130.56,122.43 130.56,78.74 127.64,75.82 120.14,75.82 118.11,77.85 118.11,101.98 122.43,106.3 122.43,109.22 124.21,111 124.21,114.55 122.05,116.71 118.49,116.71 117.73,115.95
VDD__TX on TOP: 88.77,91.82 88.77,89.79 88.14,89.15 88.14,88.01 87.88,87.76 86.23,87.76 85.34,88.65 85.34,91.44 85.85,91.95 88.65,91.95
VDD_CORE_AVS on TOP: 48.13,50.29 47.5,49.66 45.34,49.66 45.34,51.94 45.59,52.2 45.59,52.45 45.34,52.7 45.34,55.12 47.37,55.12 48.13,54.36 50.16,54.36 50.55,53.98 50.55,50.67 50.16,50.29
VDD_CORE_AVS on LY3: 46.35,84.96 46.35,82.93 45.85,82.42 45.85,82.3 46.23,81.92 46.23,81.14 45.73,80.64 45.73,79.64 45.82,79.56 46.1,79.56 46.23,79.68 46.23,79.88 47.24,80.9 49.55,80.9 50.17,80.27 50.18,80.26 50.29,80.26 50.31,80.28 50.67,80.28 50.68,80.27 50.8,80.39 50.8,80.64 51.57,81.41 51.57,82.46 52.78,83.68 52.78,84.74 51.68,85.85 47.88,85.85 47.24,85.22 46.61,85.22
VDD_CORE_AVS on LY5_PWR: 52.2,79.76 48.26,79.76 47.75,79.25 45.72,79.25 45.34,79.63 45.34,82.04 45.97,82.68 45.97,84.58 47.24,85.85 49.28,85.85 49.78,86.36 49.78,90.93 69.22,90.93 69.22,54.86 64.01,49.66 64.01,39.12 45.59,39.12 45.59,54.99 44.96,55.63 44.96,60.45 48.64,64.14 50.67,64.14 50.93,63.88 51.82,63.88 52.58,64.64 59.82,64.64 61.72,66.55 61.72,70.23 61.98,70.48 61.98,73.79 58.29,77.47 58.29,78.87 56.77,80.39 52.83,80.39
VDD_CORE_SW0 on TOP: 44.2,49.66 43.31,49.66 43.05,49.91 43.05,51.31 42.67,51.69 40.26,51.69 40.26,51.94 44.2,51.94
VDD_CORE_SW1 on TOP: 44.2,54.99 43.31,54.99 43.05,54.74 43.05,53.34 42.67,52.96 40.26,52.96 40.26,52.7 44.2,52.7
VDD_DDR_1V35 on TOP: 12.45,48.13 12.19,48.13 12.19,50.16 11.81,50.55 11.81,58.04 12.32,58.55 14.35,58.55 14.99,57.91 14.99,57.53 14.1,56.64 14.1,53.21 13.59,52.7 13.59,49.4 13.21,49.02 12.45,49.02
VDD_DDR_1V35 on TOP: 31.11,54.48 31.75,55.12 33.91,55.12 33.91,52.83 33.66,52.58 29.46,52.58 29.21,52.83 29.21,54.1 29.59,54.48
VDD_DDR_1V35 on BOTTOM: 21.46,65.66 4.57,65.66 4.32,65.41 4.32,62.87 10.1,57.09 10.1,49.59 10.79,48.9 15.62,48.9 16.76,50.04 16.76,58.67 21.46,63.37
VDD_DDR_1V35 on LY5_PWR: 45.72,83.44 45.72,84.58 47.24,86.11 49.28,86.11 49.4,86.23 49.4,103.06 4.25,103.06 4.25,103 0.76,103 0.64,102.87 0.64,48.26 28.83,48.26 28.83,51.94 29.46,52.58 32.13,52.58 32.64,53.09 32.64,58.93 31.69,59.88 31.69,72.07 31.62,72.14 31.62,73.15 38.99,80.52 44.07,80.52 45.09,81.53 45.09,82.8
VDD_DDR_SW3 on TOP: 35.05,54.99 35.94,54.99 36.2,54.74 36.2,53.34 36.58,52.96 38.99,52.96 38.99,52.7 35.05,52.7
VDD_DSP_AVS on TOP: 31.11,50.29 31.75,49.66 33.91,49.66 33.91,51.94 33.66,52.2 29.97,52.2 29.59,51.82 29.59,50.29
VDD_DSP_AVS on BOTTOM: 49.02,79.38 49.78,80.14 51.18,80.14 51.56,79.76 51.56,78.61 50.55,77.6 49.02,77.6 48.26,78.36 48.26,78.61 48.39,78.74 48.77,78.74 49.02,78.99
VDD_DSP_AVS on BOTTOM: 54.74,68.07 54.74,69.47 55.12,69.85 59.69,69.85 60.2,70.36 60.2,70.99 57.91,73.28 55.63,73.28 53.98,71.63 53.98,68.07
VDD_DSP_AVS on LY3: 34.11,75.49 32.94,74.32 32.94,66.26 33.49,65.71 40.89,65.71 41.35,66.17 41.35,69.93 42.8,71.37 42.8,74.04 41.35,75.49
VDD_DSP_AVS on LY4: 48.9,79.5 48.9,78.74 49.15,78.49 49.53,78.49 49.91,78.11 49.91,77.6 48.26,75.95 48.26,67.94 47.75,67.44 33.66,67.44 33.02,66.8 33.02,63.12 33.4,62.74 53.59,62.74 56.26,65.41 56.26,77.09 55.88,77.47 53.72,77.47 52.7,78.49 52.7,79.12 52.2,79.63 49.02,79.63
VDD_DSP_AVS on LY5_PWR: 40.32,74.37 44.52,78.57 45.28,79.19 47.94,79.2 48.39,79.63 56.39,79.63 57.21,78.81 57.21,78.23 57.28,78.16 57.28,76.83 59.5,74.61 60.08,74.03 60.08,72.39 59.82,72.13 59.82,71.25 60.08,70.99 60.08,70.35 59.04,69.32 59.04,66.31 58.39,65.66 51.05,65.66 50.55,65.15 45.59,65.15 43.18,62.74 43.18,53.47 42.8,53.09 42.8,50.42 41.53,49.15 38.61,49.15 37.97,49.78 35.69,49.78 34.16,48.26 30.23,48.26 29.21,49.28 29.21,51.82 29.72,52.32 32.51,52.32 33.02,52.83 33.02,60.07 32.64,60.45 32.64,72.39 34.61,74.37
VDD_DSP_SW2 on TOP: 35.05,49.66 35.94,49.66 36.2,49.91 36.2,51.31 36.58,51.69 38.99,51.69 38.99,51.94 35.05,51.94
VDD_SPK on TOP: 22.23,50.16 22.23,48.9 21.46,48.13 21.46,47.12 21.72,46.86 22.61,46.86 22.99,46.48 27.56,46.48 27.81,46.74 27.81,47.62 27.3,48.13 24.26,48.13 23.62,48.77 23.62,50.16
VDD_TAS on TOP: 21.97,50.16 21.97,49.15 21.21,48.39 21.21,47.12 20.83,46.74 17.78,46.74 17.27,47.24 17.27,54.86 18.41,56.01 21.84,56.01 22.61,55.24 22.61,53.21 22.23,53.21 22.23,53.98 20.7,53.98 19.68,52.96 19.68,50.16
VDD_VID on LY3: 87.25,79.63 94.49,79.63 96.14,77.98 98.42,77.98 100.84,80.39 100.84,88.01 99.57,89.28 86.87,89.28 86.23,88.65 86.23,82.8 86.87,82.17 86.87,80.01
VDDS_1V8 on TOP: 66.42,95.25 68.71,95.25 68.96,95 68.96,93.09 68.45,92.58 67.31,92.58 67.06,92.84 67.06,93.98 66.42,94.61
VDDS_1V8 on BOTTOM: 61.85,72.39 60.83,72.39 59.31,73.91 59.31,74.68 59.18,74.8 54.99,74.8 53.21,76.58 51.56,76.58 50.93,77.22 50.93,77.98 51.18,78.23 52.07,78.23 52.2,78.11 53.34,78.11 53.85,78.61 60.2,78.61 63.75,75.06 68.71,75.06 71.5,72.26 87.12,72.26 88.33,71.06 88.33,55.94 87.12,54.74 75.69,54.74 73.66,56.77 73.66,62.74 71.37,65.02 69.22,65.02 64.9,69.34 63.12,69.34 62.61,69.85 62.61,71.63
VDDS_1V8 on BOTTOM: 44.83,78.49 44.58,78.23 40.89,78.23 40.89,78.99 39.12,78.99 38.73,78.61 38.73,74.68 35.81,74.68 35.81,78.36 37.47,80.01 37.47,81.79 38.23,82.55 39.62,82.55 40.51,83.44 44.58,83.44 44.83,83.19
VDDS_1V8 on LY3: 66.42,93.09 66.42,101.47 67.69,102.74 74.8,102.74 75.56,103.5 75.56,106.43 70.36,111.63 70.36,114.55 71.12,115.32 75.82,115.32 79.63,111.51 79.63,101.35 72.9,94.61 70.99,94.61 68.96,92.58 66.93,92.58
VDDS_1V8 on LY3: 52.83,85.72 55.12,85.72 55.5,85.34 55.5,83.19 55.12,82.8 52.96,82.8 52.7,83.06 52.7,83.57 52.96,83.82 52.96,84.84 52.7,85.09 52.7,85.6
VDDS_1V8 on LY4: 44.58,83.82 44.2,83.44 43.81,83.44 38.61,78.23 38.61,78.11 38.35,77.85 36.83,77.85 35.31,76.33 35.31,74.8 35.94,74.17 38.61,74.17 42.42,77.98 44.07,77.98 44.45,77.6 48.51,77.6 49.15,78.23 48.77,78.61 48.77,79.63 49.02,79.88 52.2,79.88 52.96,79.12 52.96,78.49 53.72,77.72 56.13,77.72 56.64,77.22 56.64,68.96 61.34,64.26 72.14,64.26 77.22,59.18 91.95,59.18 93.98,61.21 100.58,61.21 104.52,65.15 104.52,83.44 99.31,88.65 53.59,88.65 51.82,86.87 46.61,86.87 46.61,87.88 45.34,87.88 44.58,87.12
VDDS_1V8 on LY5_PWR: 35.43,76.07 39.12,79.76 43.88,79.76 43.91,79.73 44.73,79.73 44.96,79.5 44.96,79.25 44.2,78.49 42.29,78.49 42.04,78.23 42.04,76.89 39.83,74.68 35.69,74.68 35.43,74.93
VDDS_1V8 on LY5_PWR: 69.6,54.86 85.47,54.86 86.36,55.75 86.36,64.14 84.84,65.66 76.07,65.66 75.95,65.79 75.95,74.17 100.97,74.17 103.25,76.45 103.25,98.04 101.6,99.69 87.63,99.69 87,99.06 87,95.25 85.72,93.98 79.88,93.98 79.88,98.55 60.2,98.55 60.2,91.31 69.6,91.31
VDA_PHY_1V8 on TOP: 73.15,101.98 73.15,100.46 73.53,100.08 73.53,98.93 73.79,98.68 74.55,98.68 74.93,99.06 74.93,101.6 74.55,101.98
VDA_PLL_1V8 on TOP: 66.29,101.98 66.29,100.46 66.67,100.08 66.67,98.93 66.93,98.68 67.69,98.68 68.07,99.06 68.07,101.6 67.69,101.98
VDA_SDIO_DV on TOP: 70.48,98.04 70.48,95.76 71.5,94.74 72.39,94.74 72.39,95.89 72.64,96.14 72.64,96.52 72.26,96.9 72.26,97.92 72.14,98.04
VIO_3V3 on TOP: 72.39,34.16 72.39,36.45 72.14,36.7 72.14,37.85 71.37,38.61 38.35,38.61 33.66,43.31 27.43,43.31 26.42,44.32 26.42,45.72 27.05,46.35 37.47,46.35 41.78,42.04 72.14,42.04 74.68,39.5 74.68,35.05 73.79,34.16
VIO_3V3 on TOP: 116.2,105.03 116.2,103.25 116.46,103 116.97,103 117.35,103.38 117.35,105.03
VIO_3V3 on BOTTOM: 43.43,117.47 49.4,117.47 51.94,114.94 51.94,108.97 49.4,108.97 48.77,108.33 46.1,108.46 44.32,110.24 44.32,111.38 42.16,113.54 42.16,116.2
VIO_3V3 on BOTTOM: 22.1,53.21 22.1,55.5 23.37,56.77 27.81,56.77 28.32,56.26 28.32,44.7 27.69,44.07 26.54,44.07 25.91,44.7 25.91,51.94 24.64,53.21
VIO_3V3 on BOTTOM: 46.23,80.01 46.23,79.5 46.86,78.87 46.86,78.11 45.85,78.11 44.83,77.09 44.83,75.95 44.45,75.56 41.91,75.56 41.78,75.69 41.78,77.98 44.83,77.98 45.09,78.23 45.09,80.77 45.47,80.77
VIO_3V3 on LY3: 45.72,88.52 45.72,89.03 46.1,89.41 48.9,89.41 49.34,89.85 49.34,92.52 52.45,95.63 55.63,95.63 56.26,95 56.26,89.53 52.7,85.98 47.75,85.98 47.24,85.47 46.48,85.47 46.1,85.09 46.1,82.93 45.72,82.55 45.72,82.3 46.1,81.92 46.1,81.15 45.59,80.64 45.59,78.36 45.85,78.11 48.01,78.11 48.64,78.74 51.56,78.74 52.32,77.98 53.09,77.98 53.47,78.36 53.47,78.74 53.34,78.87 53.09,78.87 52.32,79.63 52.32,79.88 52.96,80.52 52.96,81.92 53.21,82.17 54.86,82.17 55.37,81.66 55.37,77.09 54.86,76.58 49.78,76.58 48.64,75.44 44.45,75.44 42.67,77.22 34.04,77.22 33.02,78.23 33.02,80.01 33.91,80.9 44.32,80.9 44.32,82.17 44.96,82.8 44.96,87.76
VIO_3V3 on LY4: 66.29,69.09 73.91,69.09 77.09,65.91 85.6,65.91 86.23,66.55 86.23,69.34 69.85,85.72 54.36,85.72 52.96,84.33 52.96,83.95 53.59,83.31 53.59,81.41 55.37,79.63 62.74,79.63 64.64,77.72 64.64,70.74
VIO_3V3 on LY5_PWR: 64.52,49.66 69.34,54.48 85.72,54.48 86.74,55.5 86.74,64.39 85.09,66.04 76.58,66.04 76.33,66.29 76.33,73.53 76.58,73.79 101.22,73.79 103.63,76.2 103.63,98.17 101.73,100.08 87.38,100.08 86.49,99.19 86.49,95.38 85.47,94.36 80.26,94.36 80.26,98.93 59.82,98.93 59.82,91.31 49.78,91.31 49.78,103.38 0.64,103.38 0.64,127 84.33,127 84.33,115.57 85.6,114.3 112.27,114.3 117.09,109.47 117.09,103.38 119.51,100.97 119.51,75.95 111.25,67.69 111.25,65.91 109.28,63.94 105.35,63.94 104.78,63.37 104.78,60.96 105.54,60.2 111.51,60.2 114.3,62.99 120.27,62.99 121.79,61.47 121.79,38.99 75.56,38.99 75.56,34.16 75.44,34.04 64.52,34.04
VIO_3V3_SD on LY3: 115.7,97.03 112.52,97.03 112.46,96.96 110.93,96.96 108.2,94.23 108.2,88.52 106.81,87.12 106.81,82.68 106.93,82.55 108.84,82.55 109.6,83.31 109.6,86.11 111.89,88.39 115.32,88.39 115.7,88.77
VSYS_3V3 on TOP: 71.12,26.92 68.33,26.92 68.07,27.18 68.07,30.99 68.45,31.37 70.23,31.37 70.48,31.11 70.48,27.94 70.61,27.81 71.12,27.81
VSYS_3V3 on TOP: 38.99,51.44 36.7,51.44 36.45,51.18 36.45,49.66 36.2,49.4 35.18,49.4 34.92,49.15 34.92,47.12 35.31,46.74 36.7,46.74 37.21,47.24 37.21,49.91 37.08,50.04 37.08,51.18 38.99,51.18
VSYS_3V3 on TOP: 10.48,42.61 10.92,43.05 12.95,43.05 13.08,43.18 13.08,44.58 12.57,45.09 12.57,45.97 16.64,45.97 17.53,45.09 17.53,42.29 16.76,41.53 10.79,41.53 10.48,41.85
VSYS_3V3 on TOP: 71.12,38.23 71.12,36.07 70.99,36.07 70.99,33.91 68.45,33.91 67.88,33.34 66.04,33.34 66.04,36.45 67.82,38.23
VSYS_3V3 on TOP: 65.15,95.25 64.26,95.25 63.88,94.87 63.88,94.49 63.75,94.36 62.36,94.36 62.1,94.11 62.1,92.96 62.36,92.71 64.39,92.71 64.64,92.96 64.64,94.11 65.15,94.61
VSYS_3V3 on TOP: 25.78,30.73 18.67,30.73 18.29,31.11 17.53,31.11 16.13,29.72 16.13,24.13 15.56,23.56 6.16,23.56 5.08,24.64 5.08,26.92 12.7,34.54 25.78,34.54
VSYS_3V3 on TOP: 40.26,51.44 42.55,51.44 42.8,51.18 42.8,49.66 43.05,49.4 44.07,49.4 44.32,49.15 44.32,47.12 43.94,46.74 42.55,46.74 42.04,47.24 42.04,49.91 42.16,50.04 42.16,51.18 40.26,51.18
VSYS_3V3 on TOP: 39.5,53.85 39.5,58.67 39.24,58.93 38.1,58.93 37.85,58.67 37.85,53.87 37.87,53.85
VSYS_3V3 on TOP: 40.26,53.21 42.55,53.21 42.8,53.47 42.8,54.99 43.05,55.24 44.07,55.24 44.32,55.5 44.32,59.05 43.94,59.44 42.42,59.44 42.04,59.05 42.04,54.74 42.16,54.61 42.16,53.47 40.26,53.47
VSYS_3V3 on TOP: 38.99,53.21 36.7,53.21 36.45,53.47 36.45,54.99 36.2,55.24 35.18,55.24 34.92,55.5 34.92,58.67 35.43,59.18 36.58,59.18 37.21,58.55 37.21,54.74 37.08,54.61 37.08,53.47 38.99,53.47
VSYS_3V3 on TOP: 66.29,103.25 66.29,104.78 66.67,105.16 66.67,106.3 66.93,106.55 67.69,106.55 68.07,106.17 68.07,103.63 67.69,103.25
VSYS_3V3 on TOP: 73.15,103.25 73.15,104.78 73.53,105.16 73.53,106.3 73.79,106.55 74.55,106.55 74.93,106.17 74.93,103.63 74.55,103.25
VSYS_3V3 on LY3: 34.99,21.91 32.77,19.68 32.77,10.79 0.64,10.79 0.64,127 40.39,127 40.39,111.63 42.42,109.6 54.48,109.6 56.39,107.7 73.41,107.7 75.06,106.05 75.06,103.76 74.55,103.25 67.18,103.25 65.66,101.73 65.66,92.33 65.28,91.95 61.85,91.95 50.04,103.76 10.16,103.76 4.57,98.17 4.57,63.25 6.48,61.34 43.05,61.34 43.69,60.71 46.61,60.71 49.4,57.91 49.4,52.96 51.18,51.18 52.7,51.18 57.02,46.86 62.87,46.86 63.5,46.23 71.63,46.23 73.28,44.58 73.28,36.2 70.1,33.02 70.1,31.24 73.6,27.75 73.6,25.34 73.15,24.89 72.14,24.89 69.09,21.84 67.31,21.84 67.25,21.91
VSYS_3V3 on LY4: 34.04,15.37 40.13,15.37 41.78,17.02 41.78,19.3 40.01,21.08 35.18,21.08 33.27,19.18 33.27,16.13
VSYS_3V3 on LY5_PWR: 39.62,16.64 39.62,38.99 44.7,38.99 44.7,48.64 44.2,49.15 42.8,49.15 41.78,48.13 40.39,48.13 40.32,48.07 38.54,48.07 37.21,49.4 35.81,49.4 34.29,47.88 0.64,47.88 0.64,10.79 15.62,10.79 15.62,20.83 29.84,20.83 34.04,16.64
VSYS_5V0 on TOP: 71.37,25.65 71.37,20.45 72.2,19.62 72.26,19.68 74.93,19.68 75.69,20.45 75.69,22.23 75.31,22.61 73.41,22.61 73.15,22.86 73.15,24.26 72.14,24.26 71.75,24.64 71.75,25.65
VSYS_5V0 on LY3: 33.02,19.56 33.02,10.79 132.72,10.79 132.72,127 40.77,127 40.77,111.76 42.55,109.98 54.74,109.98 56.39,108.33 69.47,108.33 69.85,108.71 69.85,114.94 70.61,115.7 76.2,115.7 80.39,111.51 80.39,101.22 73.28,94.11 72.14,94.11 71.5,93.47 71.5,92.46 72.14,91.82 74.04,91.82 76.2,93.98 80.14,93.98 85.09,98.93 114.68,98.93 116.33,97.28 116.33,88.77 115.57,88.01 112.01,88.01 109.98,85.98 109.98,68.33 101.47,59.82 101.47,48.51 95.25,42.29 80.01,42.29 70.48,32.77 70.48,31.5 74.04,27.94 74.04,25.15 73.41,24.51 72.39,24.51 69.34,21.46 34.92,21.46
VTT_DDR on TOP: 21.34,61.66 13.53,61.66 11.43,59.56 11.43,50.55 11.94,50.04 11.94,48.13 11.56,48.13 11.56,49.28 11.18,49.66 10.54,49.66 10.03,49.15 7.87,49.15 7.62,49.4 7.62,49.91 7.87,50.16 8.51,50.16 9.14,50.8 9.14,57.15 4.19,62.1 4.19,67.94 4.7,68.45 21.72,68.45 22.73,67.44 22.86,67.44 22.86,63.18
VTT_DDR on BOTTOM: 3.68,66.42 3.68,67.56 4.45,68.33 20.95,68.33 21.46,67.82 21.46,66.42 21.08,66.04 4.06,66.04
N29751238 on TOP: 13.46,119.38 16.26,119.38 16.89,120.02 19.43,120.02 19.56,120.14 19.56,122.56 19.3,122.81 16,122.81 15.75,122.56 15.75,121.54 15.49,121.28 14.99,121.28 14.73,121.54 13.72,121.54 13.21,121.03 13.21,119.63
N29751250 on TOP: 6.73,120.52 6.73,121.79 10.03,121.79 10.03,122.68 12.32,122.68 12.45,122.56 12.45,119.63 12.19,119.38 11.18,119.38 10.03,120.52
N31206880 on TOP: 118.62,19.94 121.16,22.48 121.16,25.02 119.76,26.42 107.19,26.42 106.81,26.04 106.81,20.7 107.57,19.94
N31207093 on TOP: 107.82,36.32 107.82,29.46 114.43,29.46 114.43,36.32
N31208551 on TOP: 25.53,21.84 26.54,22.86 26.54,27.3 19.05,27.3 19.05,22.1 19.3,21.84
N31208551 on BOTTOM: 25.91,19.94 21.97,19.94 20.95,20.95 20.95,27.81 23.11,27.81 24,26.92 28.19,26.92 28.32,26.8 28.32,23.62 25.91,21.21
N33414534 on TOP: 71.63,26.92 71.63,28.32 72.14,28.83 72.14,31.24 70.87,31.24 70.87,28.45 71.25,28.07 71.25,26.92
N33509599 on TOP: 107.7,105.92 107.7,108.84 104.52,108.84 103.76,109.6 90.68,109.6 90.3,109.22 90.3,107.57 91.95,105.92
N33509815 on TOP: 114.81,104.9 114.55,104.65 114.55,103.12 114.3,102.87 113.79,102.87 113.41,103.25 113.41,104.52 114.3,105.41
N33509819 on TOP: 115.95,105.03 115.95,103.12 115.7,102.87 115.06,102.87 114.94,103 114.94,104.65 115.32,105.03
N33509835 on TOP: 104.52,109.22 104.52,111.76 104.9,112.14 108.33,112.14 108.33,110.36 109.6,110.36 109.86,110.11 109.86,108.2 107.57,108.2 107.57,109.09 107.44,109.22
N33510014 on TOP: 114.3,112.65 112.9,112.65 112.78,112.78 112.78,115.95 113.67,116.84 114.43,116.84 114.81,116.46 114.81,115.44 115.19,115.06 115.19,113.54
N33510014 on BOTTOM: 126.62,115.06 124.59,115.06 122.3,117.35 116.59,117.35 115.32,116.08 115.32,114.05 114.55,113.28 113.03,113.28 112.14,114.17 112.14,117.09 115.7,120.65 125.48,120.65 126.87,119.25 126.87,115.32
N33510050 on TOP: 116.33,113.54 116.33,114.68 115.06,115.95 115.06,116.59 115.44,116.97 116.59,116.97 117.6,115.95 117.6,113.54
N33510050 on BOTTOM: 122.3,114.94 120.52,114.94 119.63,114.05 116.59,114.05 115.7,114.94 115.7,115.95 116.84,117.09 122.05,117.09 122.81,116.33 122.81,115.44

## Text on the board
BOTTOM: PWB 518871 REV B | LOGIC 518872 REV B | LAYER 6
Board Geometry/Soldermask Bottom: SMS
Ref Des/Silkscreen Bottom: GND | CSI-IN | 1 | ASSY 518870 REV | S/N | DISP OUT | 40 | SD-CARD | NOT FCC APPROVED FOR RESALE | FOR EVALUATION ONLY; | A | BSLK
User.Comments: TEXAS INSTRUMENTS | 40 | 1
Board Geometry/Outline: 10-9-18 | BREAK OFF TAB
TOP: LAYER 1
Ref Des/Assembly Top: CONN.CABLE
Board Geometry/Soldermask Top: SMC
Ref Des/Silkscreen Top: CONSOLE | GND | PWR EN | HDMI | J6-DEBUG | DISP PWM | PWR GOOD | DISP PWR | VBAT | A | 1 | BOOT | COMM | DCARD CPU BOARD | TSLK
L2_GND: LAYER 2
LY3: LAYER 3
LY4: LAYER 4
LY5_PWR: LAYER 5
USER_PART_NUM_TOP: TSLKC
USER_PART_NUM_BOTTOM: BSLKC
DISPLAY_BOTTOM: SPS
DISPLAY_TOP: SPC
User.15: ANALOG DEVICES | PLUG-ON CARD
User.18: DATE | DESIGN ENGR | PROJECT ENGR | ENGR MGR | NEXT ASSEMBLY | APPROVED | CHECKED | DRAFTING | ENGR | NONE | 1 OF 1 | 2.  REFER TO STACKUP DRAWING FOR COPPER WEIGHT. | 10. IMPEDANCE CONTROL: | 9.  ENVIRONMENTAL COMPLIANCE: | 7.  FINISHED BOARD SHALL BE FREE OF BURRS ON EDGES. | 8.  SURFACE FINISH SHALL BE IMMERSION GOLD. | 1.  TOTAL BOARD THICKNESS SHALL BE .062 +/- .007 INCHES. | 6.  DRC'S MUST BE RUN ON THE GERBERS BEFORE BUILDING BOARDS UNLESS PRIOR | 3.  MINIMUM CLEARANCE ON THE BOARD SHALL BE 4 MILS. | 5.  PLATED THRU HOLE SIZE TOLERANCES SHALL BE +/- .003 INCH. | 4.  SOLDERMASK ON BOTH SIDES OF THE BOARD SHALL BE S.M.O.B.C., LPI, COLOR GREEN. | NOTES: UNLESS OTHERWISE SPECIFIED | AVERAGE COPPER ON THE WALL OF THE | PLATED HOLE SHALL BE PER IPC CLASS 2. | LEAD (PB)-FREE, ROHS, AND REACH COMPLIANT WITHOUT EXEMPTIONS. | REFER TO STACKUP DRAWING FOR IMPEDANCE CONTROL. | APPROVAL IS GIVEN IN WRITING. | UNPLATED THRU HOLE SIZE TOLERANCES SHALL BE +/- .002 INCH. | ALL MATERIAL SHALL BE NEMA GRADE FR-4 OR EQUIVALENT, TG>=170C, | FLAMMABILITY, 94V-0. | MINIMUM TRACE WIDTH ON THE BOARD SHALL BE 4 MILS. | A | VIEW | SCALE: NONE | TEXAS INSTRUMENTS | LAYER 1 | LAYER 2 | LAYER 5 | LAYER 6 | A-A
User.19: RICHARDSON,TEXAS 75081 | 1510 N. PLANO RD | (972)931-4100 | SUITE 300 | QC GRAPHICS INC. | DATE | DESIGN ENGR | PROJECT ENGR | ENGR MGR | NEXT ASSEMBLY | APPROVED | CHECKED | DRAFTING | ENGR | 2 OF 2 | TEXAS INSTRUMENTS
User.20: RICHARDSON,TEXAS 75081 | 1510 N. PLANO RD | (972)931-4100 | SUITE 300 | QC GRAPHICS INC. | NONE | FABRICATION DRAWING, | ADAS 15X15MM | TEXAS INSTRUMENTS
User.21: AUSTIN,TEXAS 78756 | 4410 SHOALWOOD | (512)260-5778 | TURNING CONCEPT | INTO REALITY
User.25: ASSEMBLY COMPONENT SIDE
User.26: ASSEMBLY SOLDER SIDE
User.31: FIGURE | SIZE | 8.0 | 10.0 | 12.0 | 13.0 | 39.0 | 40.0 | 41.0 | 41.3 | 51.0 | 55.0 | 100.0 | 125.0 | 35.0 | 118.0 | PLATED | NON-PLATED | DRILL CHART | ALL UNITS ARE IN MILS | QTY | 183 | 102 | 185 | 1468 | 6 | 10 | 12 | 2 | 4 | 8 | 1 | TOL | NOTE
